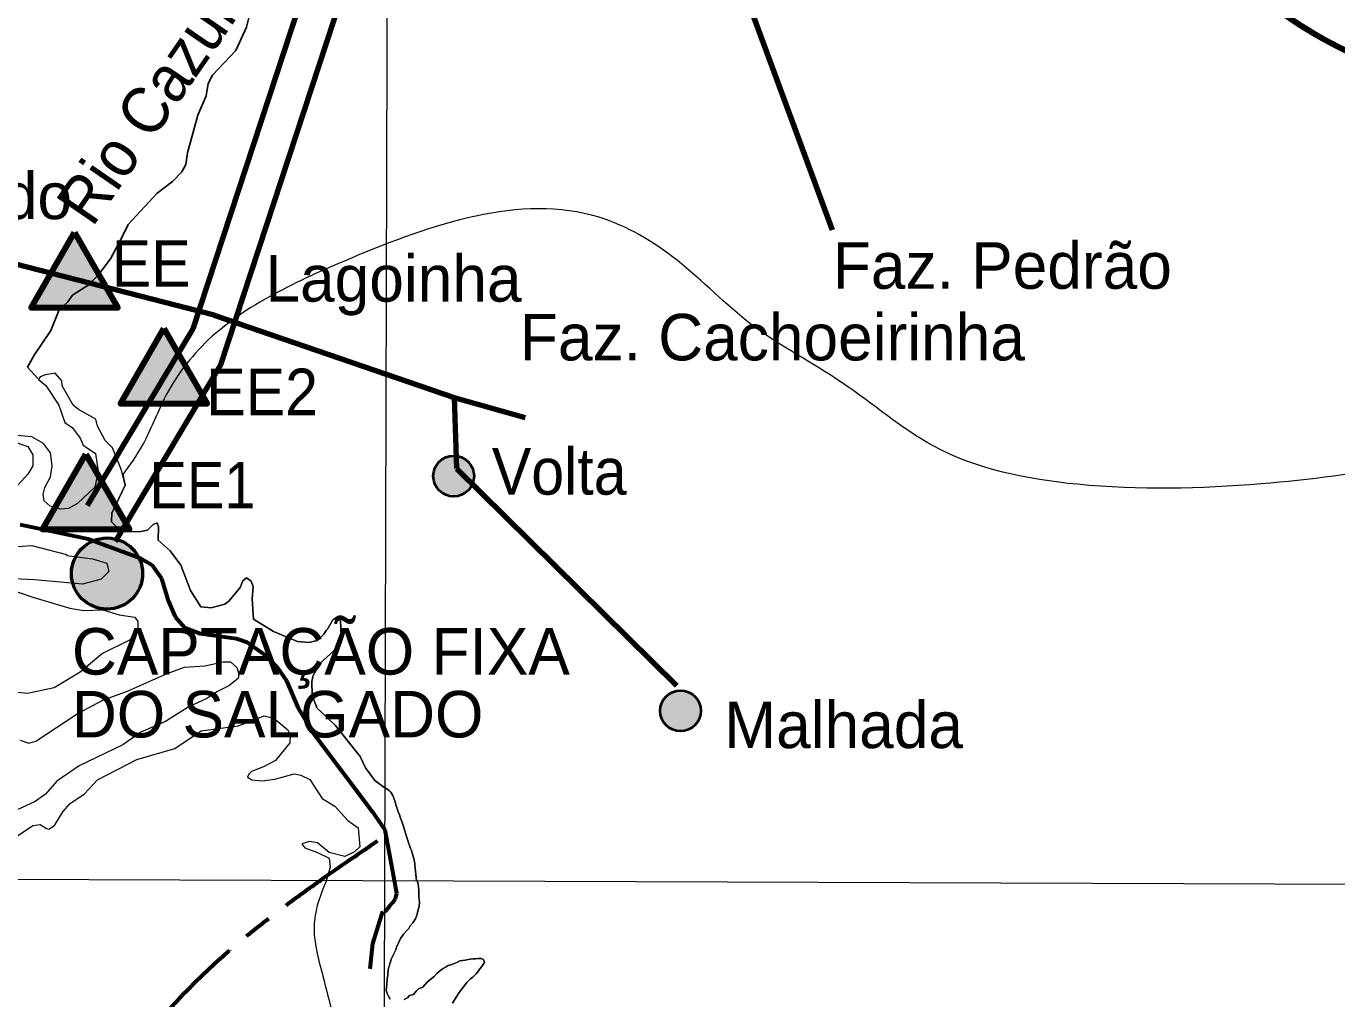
# Model space of a CAD drawing. Extents: x 553962 to 842807, y 8883888 to 9032388.
# Drawn here: x 605914 to 619995, y 8948437 to 8958889 of the extents above; entities that cross this region are included whole.
import ezdxf
from ezdxf.enums import TextEntityAlignment as Align

# ---------------------------------------------------------------- set-up
doc = ezdxf.new("R2010")
doc.units = 0
doc.header["$LTSCALE"] = 200
doc.linetypes.add('LONG_DASH_SHORT_DASH', pattern=[9.9, 6, -1.2, 1.5, -1.2])
for name, color, linetype, lineweight in [('1', 7, 'Continuous', 13), ('24', 7, 'Continuous', 25), ('25', 7, 'Continuous', 13), ('28', 7, 'Continuous', 40), ('41', 7, 'Continuous', 40), ('57', 7, 'Continuous', 13), ('7', 7, 'LONG_DASH_SHORT_DASH', 60), ('9', 7, 'Continuous', 90)]:
    doc.layers.add(name, color=color, linetype=linetype, lineweight=lineweight)
doc.layers.add('49', color=7, linetype='Continuous')

msp = doc.modelspace()

# ---------------------------------------------------------------- hatches: boundary and pattern name
at = {"layer": '28'}
for points in [[(606432.5, 8956671.2), (606898.6, 8955863.8), (605966.3, 8955863.8)], [(607392.8, 8955639.7), (607858.9, 8954832.4), (606926.7, 8954832.4)], [(606556.5, 8954288.7), (607022.6, 8953481.3), (606090.3, 8953481.3)], [(607165, 8953006.8, 1), (606400.7, 8953006.8, 1)]]:
    msp.add_hatch(color=256, dxfattribs=at).paths.add_polyline_path(points)
at = {"layer": '41'}
for points in [[(610725.8, 8954054.2, 1), (610288.2, 8954054.2, 1)], [(613162.2, 8951531.2, 1), (612724.6, 8951531.2, 1)]]:
    msp.add_hatch(color=256, dxfattribs=at).paths.add_polyline_path(points)

# ---------------------------------------------------------------- linework, layer by layer
at = {"layer": '1'}
msp.add_line((565315.3, 8949866.8), (791497.7, 8949052.2), dxfattribs=at)
msp.add_lwpolyline([(609971.9, 9023551.8), (609764.7, 8949706.7), (609734.2, 8939404.4)], dxfattribs=at)
at = {"layer": '24'}
for points in [[(606950.7, 8956641.4), (607010.7, 8956757.8), (607320.7, 8957095.6), (607486.4, 8957220.9), (607586.3, 8957325.3), (607630.8, 8957401.7), (607645.7, 8957526.8), (607756.7, 8957933.8), (607847.4, 8958140.8), (607868.9, 8958272.7), (607915.5, 8958363.8), (608166.1, 8958629.3), (608279.8, 8958879.3), (608317, 8959022.3)], [(606039.3, 8955103.8), (605929.6, 8955224.5), (605999.4, 8955353.7), (606180, 8955619.3), (606269.2, 8955840.2), (606360.2, 8955926.9), (606411.5, 8955999.5), (606589.9, 8956112.1), (606699.8, 8956226.1), (606821.6, 8956390.6), (606950.7, 8956641.4)]]:
    msp.add_lwpolyline(points, dxfattribs=at)
at = {"layer": '25'}
for points in [[(609755.4, 8950712.2), (609661.1, 8950783.5), (609561, 8950917.9), (609502.2, 8951042.1), (609232.8, 8951376.9), (609037.8, 8951563.3), (608987.2, 8951699.7), (608983.5, 8951846.5), (608997.5, 8951911.8), (609071.5, 8952043.1), (609222.8, 8952181.3), (609297.8, 8952340.2), (609292, 8952494.6), (609262.3, 8952545.1), (609208.4, 8952508.9), (609150.1, 8952407.8), (609137, 8952393.4), (609112.2, 8952354.9), (609043.5, 8952286.2), (608950.9, 8952265), (608829.5, 8952275.2), (608570.6, 8952384.4), (608354.7, 8952517.4), (608341.8, 8952734.8), (608352.3, 8952862.7), (608331.7, 8952926.3), (608281.3, 8952961.5), (608241.6, 8952927.5), (608214.1, 8952858.4), (608092.3, 8952708.4), (608046.9, 8952676.2), (607900.7, 8952638.1), (607791.6, 8952649), (607678.7, 8952823.7), (607576.2, 8953096.8), (607460.3, 8953252.1), (607330.5, 8953367), (607335.3, 8953510.5), (607319.8, 8953546.9), (607315.4, 8953548.9), (607278.7, 8953534.6), (607216.5, 8953473.1), (607127, 8953454.3), (607030.5, 8953457.3), (606882.1, 8953514.2), (606832.1, 8953564.1), (606835, 8953655.9), (606976.1, 8953957.7), (606939.6, 8954118.5), (606839.8, 8954356.2), (606764, 8954436.8), (606681.6, 8954591.6), (606663.8, 8954666.8), (606474.6, 8954769), (606419, 8954817.7), (606301.8, 8955025.5), (606297.6, 8955076.7), (606224.7, 8955160), (606120.8, 8955143.2), (606065.2, 8955120.1), (606045.1, 8955091.1), (606126.8, 8955027.9), (606264.5, 8954818.1), (606327.6, 8954629.3), (606412.6, 8954571)], [(606412.6, 8954571), (606492.4, 8954462.3), (606527.5, 8954387.4), (606659.3, 8954296.9), (606686, 8954102.5), (606651.8, 8953936.7), (606463.9, 8953759.9), (606370.3, 8953707.3), (606285.1, 8953700.2), (606172.6, 8953730.1), (606105.6, 8953789.7), (606098, 8953860.6), (606114.5, 8953932), (606175.8, 8954045.5), (606193.7, 8954164.2), (606175.7, 8954305.4), (606098.8, 8954404.1), (605973.2, 8954477.1), (605744.8, 8954495.8)], [(605753.2, 8954432.8), (605930.1, 8954372.2), (605986.4, 8954284.2), (605983.7, 8954165.7), (605933.2, 8954074.1), (605787.4, 8953917.3)], [(605719.6, 8953290.4), (605976.2, 8953310), (606348.4, 8953209.8), (606349.1, 8953199.3), (606627.5, 8953166), (606782.2, 8953118.9), (606803.1, 8953027.3), (606720.6, 8952947.4), (606519.6, 8952891.6), (606003.2, 8952941.1)], [(606003.2, 8952941.1), (605703.8, 8952954.5)], [(605703.8, 8952849.4), (605995.3, 8952749.3), (606381.6, 8952634.1), (606534.5, 8952611), (606739.1, 8952617.5), (606911.6, 8952561.5), (607081, 8952539.2), (607113.4, 8952492.8), (607113.5, 8952391.1), (607023.8, 8952292), (606734.5, 8952146.5), (606495.7, 8951946), (606213.2, 8951778.7), (605929, 8951719.6), (605757, 8951735)], [(605848.8, 8951216.1), (605942.1, 8951185.6), (606018, 8951204.4), (606463.2, 8951500.4), (606738.6, 8951647.1), (607011.1, 8951745.5), (607430.1, 8951933.6), (607613.6, 8951999.1), (607833.1, 8952016.1), (608030.1, 8952056.4), (608109.9, 8952056.6), (608176.9, 8951998), (608199.3, 8951925.6), (608189.8, 8951877.6), (608090.2, 8951799.8), (607960.9, 8951735.6), (607862.5, 8951666.2), (607653, 8951570.5), (607410.8, 8951418.3), (607144.4, 8951302.6), (606950.8, 8951166.6), (606482.1, 8950942.3), (606242.9, 8950775.2), (606123, 8950635.5), (606012.1, 8950556.7), (605725, 8950424.5)], [(605776.5, 8950159.4), (605984.7, 8950300.3), (606066, 8950310.7), (606133.6, 8950266.2), (606157.8, 8950260.8), (606219.7, 8950297.6), (606309.2, 8950444.5), (606386.8, 8950535.4), (606539, 8950640.6), (606679, 8950789), (607103.1, 8951009.8), (607511.4, 8951127.6), (607793.4, 8951318.1), (608189.8, 8951370), (608470.1, 8951476.1), (608576.2, 8951452.3), (608726.2, 8951326.4), (608749.8, 8951266.5), (608747.2, 8951186.9), (608590.8, 8950999.1), (608464.4, 8950928.1), (608333.9, 8950879.5), (608305.4, 8950852.7), (608293.4, 8950819), (608336.8, 8950788.8), (608450, 8950780.2), (608584.4, 8950796.9), (608792.8, 8950853.3), (608865.7, 8950839.8)], [(608865.7, 8950839.8), (608961.3, 8950792.2), (609092.6, 8950589), (609228.6, 8950508.5), (609370.6, 8950354.8), (609479, 8950274.1), (609498.7, 8950068.9), (609441.2, 8950017.2), (609336.6, 8949965), (609169.4, 8950008.4), (609042.6, 8950111.6), (608957.7, 8950128.6), (608874.2, 8950101.3), (608908.7, 8950059.5), (609044.9, 8950008.9), (609169.7, 8949947.6), (609179.8, 8949852.8), (609137, 8949702.7)], [(609792.6, 8948650.3), (609799.1, 8948692.7), (609802.3, 8948751.2), (609825.2, 8948822.9), (609838.2, 8948868.4), (609861, 8948914), (609887.1, 8948962.8), (609893.6, 8948992.1), (609916.4, 8949044.2), (609935.9, 8949083.3), (609968.5, 8949132.1), (610001.1, 8949167.9), (610023.9, 8949190.7), (610040.2, 8949220), (610069.5, 8949252.6), (610095.5, 8949294.9), (610115.1, 8949347), (610121.6, 8949382.8), (610134.6, 8949428.4), (610141.1, 8949473.9), (610130.7, 8949532.9), (610130.9, 8949558), (610131.1, 8949578), (610131.3, 8949608.1), (610129, 8949638.1), (610124.3, 8949673.2), (610117, 8949693.3), (610108.9, 8949704.2)], [(610493.9, 8948389.1), (610533.4, 8948456.2), (610564.5, 8948504.9), (610611, 8948567), (610646.5, 8948613.2), (610686.8, 8948650.5), (610711.9, 8948670.4), (610749.7, 8948705.2), (610767.4, 8948727.6), (610787.7, 8948760), (610807.8, 8948782.4), (610838.2, 8948827.3), (610825.9, 8948859.9), (610803.5, 8948870.1), (610771, 8948870.3), (610741, 8948868), (610720.9, 8948865.6), (610683.4, 8948863.3), (610663.3, 8948858.5), (610630.8, 8948853.7), (610600.7, 8948848.9), (610573.2, 8948846.6), (610540.6, 8948826.7), (610505.4, 8948814.5), (610475.3, 8948802.1), (610447.8, 8948794.8), (610427.6, 8948779.9), (610392.5, 8948762.6), (610372.4, 8948747.7), (610330.1, 8948712.2), (610330.1, 8948712.2), (610297.5, 8948676.4), (610297.5, 8948676.4), (610248.6, 8948637.3), (610219.3, 8948611.3), (610219.3, 8948611.3), (610193.3, 8948585.2), (610173.7, 8948562.4), (610128.1, 8948542.9), (610102.1, 8948520.1), (610076, 8948484.3), (610033.6, 8948471.3), (610010.8, 8948448.5), (609975, 8948429)], [(609825.2, 8948432.2), (609808.9, 8948458.3), (609808.9, 8948458.3), (609789.3, 8948500.6), (609782.8, 8948533.1), (609789.3, 8948588.5), (609792.6, 8948650.3)]]:
    msp.add_lwpolyline(points, dxfattribs=at)
for points in [[(610108.9, 8949704.2), (610092.8, 8949844.8), (610081.3, 8949930.9), (610018.2, 8950125.9), (609960.9, 8950309.5), (609886.3, 8950521.8), (609817.5, 8950670.9), (609755.4, 8950712.2)], [(609137, 8949702.7), (609010, 8949279.3), (609102.4, 8948678.5), (609204.1, 8948290.3), (609407.4, 8947735.7), (609657, 8947365.9), (609757.5, 8947308.3)]]:
    msp.add_spline(points, degree=3, dxfattribs=at)
at = {"layer": '28', "lineweight": 80}
for p, q in [((612881.2, 8961293.3), (614572.2, 8956699.9)), ((607932.3, 8955784.8), (599942.3, 8957828.5)), ((610512, 8954900.5), (610535.9, 8954135.6)), ((610535.9, 8954135.6), (612900.6, 8951805.2))]:
    msp.add_line(p, q, dxfattribs=at)
for points in [[(609654.9, 8961582), (607705.3, 8955637.1), (606570.7, 8953736.9)], [(610035, 8961447.4), (608003.1, 8955251.4), (606868.5, 8953351.2)], [(607932.3, 8955784.8), (610512, 8954900.5), (611276.4, 8954685.3)]]:
    msp.add_lwpolyline(points, dxfattribs=at)
at = {"layer": '28', "lineweight": 90}
for points in [[(606432.5, 8956671.2), (606898.6, 8955863.8), (605966.3, 8955863.8)], [(607392.8, 8955639.7), (607858.9, 8954832.4), (606926.7, 8954832.4)], [(606556.5, 8954288.7), (607022.6, 8953481.3), (606090.3, 8953481.3)]]:
    msp.add_lwpolyline(points, close=True, dxfattribs=at)
at = {"layer": '28', "lineweight": 53}
msp.add_circle((606782.8, 8953006.8), 382.2, dxfattribs=at)
at = {"layer": '41'}
for centre in [(610507, 8954054.2), (612943.4, 8951531.2)]:
    msp.add_circle(centre, 218.8, dxfattribs=at)
at = {"layer": '57'}
for points in [[(606950.6, 8954069.9), (606976.1, 8953957.7), (606835, 8953655.9), (606832.1, 8953564.1), (606882.1, 8953514.2), (607030.5, 8953457.3), (607127, 8953454.3), (607216.5, 8953473.1), (607278.7, 8953534.6), (607315.4, 8953548.9), (607319.8, 8953546.9), (607335.3, 8953510.5), (607330.5, 8953367), (607460.3, 8953252.1), (607576.2, 8953096.8), (607678.7, 8952823.7), (607791.6, 8952649), (607900.7, 8952638.1), (608046.9, 8952676.2), (608092.3, 8952708.4), (608214.1, 8952858.4), (608241.6, 8952927.5), (608281.3, 8952961.5), (608331.7, 8952926.3), (608352.3, 8952862.7), (608341.8, 8952734.8), (608354.7, 8952517.4), (608570.6, 8952384.4), (608829.5, 8952275.2), (608950.9, 8952265), (609043.5, 8952286.2), (609112.2, 8952354.9), (609137, 8952393.4), (609150.1, 8952407.8), (609208.4, 8952508.9), (609262.3, 8952545.1), (609292, 8952494.6), (609297.8, 8952340.2), (609222.8, 8952181.3), (609071.5, 8952043.1), (608997.5, 8951911.8), (608983.5, 8951846.5), (608987.2, 8951699.7), (609037.8, 8951563.3), (609232.8, 8951376.9), (609502.2, 8951042.1), (609561, 8950917.9), (609661.1, 8950783.5), (609755.4, 8950712.2)], [(606950.6, 8954069.9), (606976.1, 8953957.7), (606835, 8953655.9), (606832.1, 8953564.1), (606882.1, 8953514.2), (607030.5, 8953457.3), (607127, 8953454.3), (607216.5, 8953473.1), (607278.7, 8953534.6), (607315.4, 8953548.9), (607319.8, 8953546.9), (607335.3, 8953510.5), (607330.5, 8953367), (607460.3, 8953252.1), (607576.2, 8953096.8), (607678.7, 8952823.7), (607791.6, 8952649), (607900.7, 8952638.1), (608046.9, 8952676.2), (608092.3, 8952708.4), (608214.1, 8952858.4), (608241.6, 8952927.5), (608281.3, 8952961.5), (608331.7, 8952926.3), (608352.3, 8952862.7), (608341.8, 8952734.8), (608354.7, 8952517.4), (608570.6, 8952384.4), (608829.5, 8952275.2), (608950.9, 8952265), (609043.5, 8952286.2), (609112.2, 8952354.9), (609137, 8952393.4), (609150.1, 8952407.8), (609208.4, 8952508.9), (609262.3, 8952545.1), (609292, 8952494.6), (609297.8, 8952340.2), (609222.8, 8952181.3), (609071.5, 8952043.1), (608997.5, 8951911.8), (608983.5, 8951846.5), (608987.2, 8951699.7), (609037.8, 8951563.3), (609232.8, 8951376.9), (609502.2, 8951042.1), (609561, 8950917.9), (609661.1, 8950783.5), (609755.4, 8950712.2)], [(610108.9, 8949704.2), (610117, 8949693.3), (610124.3, 8949673.2), (610129, 8949638.1), (610131.3, 8949608.1), (610131.1, 8949578), (610130.9, 8949558), (610130.7, 8949532.9), (610141.1, 8949473.9), (610134.6, 8949428.4), (610121.6, 8949382.8), (610115.1, 8949347), (610095.5, 8949294.9), (610069.5, 8949252.6), (610040.2, 8949220), (610023.9, 8949190.7), (610001.1, 8949167.9), (609968.5, 8949132.1), (609935.9, 8949083.3), (609916.4, 8949044.2), (609893.6, 8948992.1), (609887.1, 8948962.8), (609861, 8948914), (609838.2, 8948868.4), (609825.2, 8948822.9), (609802.3, 8948751.2), (609799.1, 8948692.7), (609792.6, 8948650.3)], [(610108.9, 8949704.2), (610117, 8949693.3), (610124.3, 8949673.2), (610129, 8949638.1), (610131.3, 8949608.1), (610131.1, 8949578), (610130.9, 8949558), (610130.7, 8949532.9), (610141.1, 8949473.9), (610134.6, 8949428.4), (610121.6, 8949382.8), (610115.1, 8949347), (610095.5, 8949294.9), (610069.5, 8949252.6), (610040.2, 8949220), (610023.9, 8949190.7), (610001.1, 8949167.9), (609968.5, 8949132.1), (609935.9, 8949083.3), (609916.4, 8949044.2), (609893.6, 8948992.1), (609887.1, 8948962.8), (609861, 8948914), (609838.2, 8948868.4), (609825.2, 8948822.9), (609802.3, 8948751.2), (609799.1, 8948692.7), (609792.6, 8948650.3)], [(609975, 8948429), (610010.8, 8948448.5), (610033.6, 8948471.3), (610076, 8948484.3), (610102.1, 8948520.1), (610128.1, 8948542.9), (610173.7, 8948562.4), (610193.3, 8948585.2), (610219.3, 8948611.3), (610219.3, 8948611.3), (610248.6, 8948637.3), (610297.5, 8948676.4), (610297.5, 8948676.4), (610330.1, 8948712.2), (610330.1, 8948712.2), (610372.4, 8948747.7), (610392.5, 8948762.6), (610427.6, 8948779.9), (610447.8, 8948794.8), (610475.3, 8948802.1), (610505.4, 8948814.5), (610540.6, 8948826.7), (610573.2, 8948846.6), (610600.7, 8948848.9), (610630.8, 8948853.7), (610663.3, 8948858.5), (610683.4, 8948863.3), (610720.9, 8948865.6), (610741, 8948868), (610771, 8948870.3), (610803.5, 8948870.1), (610825.9, 8948859.9), (610838.2, 8948827.3), (610807.8, 8948782.4), (610787.7, 8948760), (610767.4, 8948727.6), (610749.7, 8948705.2), (610711.9, 8948670.4), (610686.8, 8948650.5), (610646.5, 8948613.2), (610611, 8948567), (610564.5, 8948504.9), (610533.4, 8948456.2), (610493.9, 8948389.1)], [(609975, 8948429), (610010.8, 8948448.5), (610033.6, 8948471.3), (610076, 8948484.3), (610102.1, 8948520.1), (610128.1, 8948542.9), (610173.7, 8948562.4), (610193.3, 8948585.2), (610219.3, 8948611.3), (610219.3, 8948611.3), (610248.6, 8948637.3), (610297.5, 8948676.4), (610297.5, 8948676.4), (610330.1, 8948712.2), (610330.1, 8948712.2), (610372.4, 8948747.7), (610392.5, 8948762.6), (610427.6, 8948779.9), (610447.8, 8948794.8), (610475.3, 8948802.1), (610505.4, 8948814.5), (610540.6, 8948826.7), (610573.2, 8948846.6), (610600.7, 8948848.9), (610630.8, 8948853.7), (610663.3, 8948858.5), (610683.4, 8948863.3), (610720.9, 8948865.6), (610741, 8948868), (610771, 8948870.3), (610803.5, 8948870.1), (610825.9, 8948859.9), (610838.2, 8948827.3), (610807.8, 8948782.4), (610787.7, 8948760), (610767.4, 8948727.6), (610749.7, 8948705.2), (610711.9, 8948670.4), (610686.8, 8948650.5), (610646.5, 8948613.2), (610611, 8948567), (610564.5, 8948504.9), (610533.4, 8948456.2), (610493.9, 8948389.1)], [(609792.6, 8948650.3), (609789.3, 8948588.5), (609782.8, 8948533.1), (609789.3, 8948500.6), (609808.9, 8948458.3), (609808.9, 8948458.3), (609825.2, 8948432.2)], [(609792.6, 8948650.3), (609789.3, 8948588.5), (609782.8, 8948533.1), (609789.3, 8948500.6), (609808.9, 8948458.3), (609808.9, 8948458.3), (609825.2, 8948432.2)]]:
    msp.add_lwpolyline(points, dxfattribs=at)
for points in [[(646003, 8949251.6), (644721.9, 8950215.5), (643492.6, 8951234.6), (642099.6, 8952556.8), (640992.4, 8953664.6), (640171, 8954236.3), (637456.5, 8955772.9), (636135, 8956237.5), (634599.2, 8956630.6), (632599.1, 8956773.5), (629063.1, 8956702), (626348.7, 8956058.8), (623953.8, 8955209.7), (622371.6, 8954682.1), (620725.9, 8954192.9), (619183.7, 8953970.3), (617209.7, 8953965.7), (615658.4, 8954379), (614681.6, 8955057.1), (613704.6, 8955684.2), (612906.2, 8956374.2), (612068.3, 8956835.4), (609416.9, 8956401.3), (608625.2, 8956035.7), (607870.9, 8955517.4), (607396.1, 8954883.6), (607164, 8954388.6), (606950.6, 8954069.9)], [(646003, 8949251.6), (644721.9, 8950215.5), (643521.3, 8951208.7), (642428.2, 8952239.5), (641741.8, 8952914.9), (640407.4, 8954089.3), (638333.9, 8955336.1), (636237.3, 8956206.4), (633646.8, 8956732.8), (631365, 8956802.2), (629312, 8956729.1), (626793.2, 8956204.6), (623953.8, 8955209.7), (622371.6, 8954682.1), (620725.9, 8954192.9), (619183.7, 8953970.3), (617209.7, 8953965.7), (615658.4, 8954379), (614681.6, 8955057.1), (613704.6, 8955684.2), (612906.2, 8956374.2), (612068.3, 8956835.4), (609416.9, 8956401.3), (608625.2, 8956035.7), (607870.9, 8955517.4), (607396.1, 8954883.6), (607164, 8954388.6), (606950.6, 8954069.9)], [(609755.4, 8950712.2), (609817.5, 8950670.9), (609886.3, 8950521.8), (609960.9, 8950309.5), (610018.2, 8950125.9), (610081.3, 8949930.9), (610092.8, 8949844.8), (610108.9, 8949704.2)], [(609755.4, 8950712.2), (609817.5, 8950670.9), (609886.3, 8950521.8), (609960.9, 8950309.5), (610018.2, 8950125.9), (610081.3, 8949930.9), (610092.8, 8949844.8), (610108.9, 8949704.2)]]:
    msp.add_spline(points, degree=3, dxfattribs=at)
at = {"layer": '7'}
for points in [[(605849.3, 8953532.9), (606579.7, 8953379.4), (607141.7, 8953171.8), (607262.6, 8953100.6), (607368.8, 8952953.3), (607440, 8952718.2), (607513.5, 8952540.9), (607615, 8952426.2), (607782.6, 8952361), (608175.1, 8952307.1), (608287.5, 8952268.2), (608473.6, 8952138.4), (608607.4, 8952004.5), (608709, 8951855.3), (608834.6, 8951559), (609001.1, 8951288.7), (609632.1, 8950450.2), (609766.1, 8950251.3)], [(609766.1, 8950251.3), (609892.1, 8949571.8), (609876.7, 8949511.8), (609848.8, 8949469.3), (609818.6, 8949432), (609785.7, 8949389.6), (609763.6, 8949371.8)], [(609608.9, 8948758.3), (609638.2, 8949029.6), (609745.9, 8949377.2)]]:
    msp.add_lwpolyline(points, dxfattribs=at)
msp.add_spline([(609688.1, 8950131.7), (607584.3, 8948466.4), (606301.7, 8946741.8), (602418.3, 8940294.4)], degree=3, dxfattribs=at)
at = {"layer": '9'}
msp.add_spline([(592698.5, 8977198.4), (599903.5, 8973292.7), (608459.2, 8968138.2), (612674.8, 8965332.6), (616842, 8962096.4), (620005, 8958671.2), (621134, 8957974.7), (621473.4, 8956805.3), (621586.2, 8956597.5)], degree=3, dxfattribs=at)

# ---------------------------------------------------------------- texts
at = {"layer": '28'}
for s, width, p in [('EE', 0.95, (606833.5, 8956088.8)), ('EE2', 0.95, (607848.9, 8954708.8)), ('EE1', 0.9, (607239.4, 8953706.9))]:
    msp.add_text(s, height=500, dxfattribs=dict(at, width=width)).set_placement(p)
for s, p in [('CAPTAÇÃO FIXA', (606404.9, 8951921)), ('DO SALGADO', (606404.9, 8951245.8))]:
    msp.add_text(s, height=500, dxfattribs=at).set_placement(p)
at = {"layer": '41'}
for s, p in [('Salgado', (603953.1, 8956815.5)), ('Faz. Pedrão', (614580.7, 8956067.1)), ('Lagoinha', (608484.5, 8955929.1)), ('Faz. Cachoeirinha', (611218.2, 8955297.5)), ('Malhada', (613414, 8951130.9))]:
    msp.add_text(s, height=500, dxfattribs=at).set_placement(p)
at = {"layer": '41', "width": 0.95}
msp.add_text('Volta', height=500, dxfattribs=at).set_placement((610916.8, 8953855))
at = {"layer": '49', "width": 0.95}
msp.add_text('Rio Cazumba', height=500, rotation=55.429, dxfattribs=at).set_placement((607716.8, 8958303), align=Align.CENTER)

doc.saveas('drawing.dxf')
